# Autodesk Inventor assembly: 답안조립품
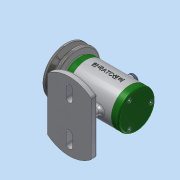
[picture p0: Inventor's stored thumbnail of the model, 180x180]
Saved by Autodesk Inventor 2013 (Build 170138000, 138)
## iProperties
Created: 2017-12
Part Number: 답안조립품
Document SubType Name: Assembly
Designer: dgall
Author: dgall
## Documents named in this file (14)
- C:\Users\dgall\Desktop\471207V1012\답안조립품.iam
- C:\Users\dgall\Desktop\471207V1012\본체.ipt
- C:\Users\dgall\Desktop\471207V1012\V벨트풀리.ipt
- C:\Users\dgall\Desktop\471207V1012\고무캡.ipt
- C:\Users\dgall\Desktop\471207V1012\너트 M 8.ipt
- C:\Users\dgall\Desktop\471207V1012\뒤커버.ipt
- C:\Users\dgall\Desktop\471207V1012\베어링 15 x 32 x 9.ipt
- C:\Users\dgall\Desktop\471207V1012\볼트 M4 x 12.ipt
- C:\Users\dgall\Desktop\471207V1012\스프링와셔 8.ipt
- C:\Users\dgall\Desktop\471207V1012\앞커버.ipt
- C:\Users\dgall\Desktop\471207V1012\오일 실 15 25 7.ipt
- C:\Users\dgall\Desktop\471207V1012\와셔 8x17.ipt
- C:\Users\dgall\Desktop\471207V1012\축.ipt
- C:\Users\dgall\Desktop\471207V1012\키 3 x 3 x 12.ipt
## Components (2 placed, 2 different names)
1. V벨트풀리:1
2. 고무캡:1
